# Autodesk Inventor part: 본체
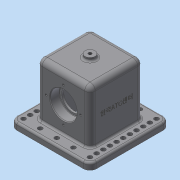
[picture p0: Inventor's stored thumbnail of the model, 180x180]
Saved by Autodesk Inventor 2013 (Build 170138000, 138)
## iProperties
Created: 2018-11
Part Number: 본체
Material: 일반
Document SubType Name: Modeling
Designer: dgall
Density: 1 g/cm^3
Author: dgall
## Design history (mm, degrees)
sketch "스케치1"
  geometry: L1 (-40, 40)-(40, 40); L2 (40, 40)-(40, -40); L3 (40, -40)-(-40, -40); L4 (-40, -40)-(-40, 40); L5 (-60, 60)-(60, 60); L6 (60, 60)-(60, -60); L7 (60, -60)-(-60, -60); L8 (-60, -60)-(-60, 60); L9 (-30, 23)-(30, 23); L10 (30, 23)-(30, -23); L11 (30, -23)-(-30, -23); L12 (-30, -23)-(-30, 23); 7 further points
  constraints: 24 end point, 6 midpoint, 6 parallel, 5 perpendicular, 3 horizontal, 3 horizontal alignment, 3 vertical alignment
  dimensions: "d0" = 80 distance of L1.start L1.end; "d2" = 120 distance of L5.start L5.end; "d14" = 60 distance of L9.start L9.end; "d15" = 46 distance of L11.end L9.start
extrude "돌출1" new body sketch "스케치1" distance "d3" = 90; taper "d4" = 0 deg
extrude "돌출2" join sketch "스케치1" distance "d5" = 10; taper "d6" = 0 deg
sketch "스케치2"
  geometry: L1 (60, 10)-(60, 0) reference; L2 (60, 0)-(-60, 0) reference; L3 (-60, 0)-(-60, 10) reference; L4 (-60, 10)-(-40, 10) reference; L5 (-40, 10)-(-40, 90) reference; L6 (-40, 90)-(40, 90) reference; L7 (40, 90)-(40, 10) reference; L8 (40, 10)-(60, 10) reference; L9 (-40, 48)-(40, 48); L10 (-40, 68)-(-26, 68); L11 (-26, 68)-(-26, 64.5); L12 (-26, 64.5)-(-23, 64.5); L13 (-23, 64.5)-(-23, 48); L14 (23, 64.5)-(26, 64.5); L15 (26, 64.5)-(26, 68); L16 (26, 68)-(40, 68); L17 (23, 64.5)-(23, 48); 1 further point
  constraints: 18 end point, 6 point on line, 5 parallel, 5 perpendicular, 3 equal length, 1 horizontal alignment
  dimensions: "d7" = 48 distance between parallel lines of L2 L9; "d8" = 14 distance of L10.start L10.end; "d9" = 3 distance of L11.end L12.end; "d11" = 40 diameter of L10 L9; "d12" = 33 diameter of L12 L9
revolve "회전1" sketch "스케치2" stored, may be unused: angle "d13" = 90 deg
extrude "돌출3" cut sketch "스케치1" distance "d16" = 80; taper "d17" = 0 deg
node "작업 평면1"
sketch "스케치5"
  geometry: C1 r 7.5 at (0, 0); 1 further point
  constraints: 1 centre point, 1 coincident
  dimensions: "d52" = 15 diameter of C1
extrude "돌출4" join sketch "스케치5" stored distance "d53" = 80; taper "d54" = 0 deg
hole "구멍3" diameter "d57" = 4.917; stored, may be unused: countersink angle "d61" = 90 deg, drill point angle "d63" = 0 deg; dims "d58" = 3, "d59" = 4, "d60" = 2, "d62" = 8, "d117" = 10, "d118" = 10
sketch "스케치6"
  geometry: C1 r 20 at (40, -42) reference; 2 further points
  constraints: 1 vertical alignment
  dimensions: "d64" = 26 distance of C1.centre point (40, -16)
hole "구멍4" sketch "스케치6" at (40, -16) diameter "d65" = 3.242; stored, may be unused: countersink angle "d69" = 90 deg, drill point angle "d71" = 118 deg; dims "d66" = 8, "d67" = 4, "d68" = 2, "d70" = 10
fillet "모깎기1" dims "d75" = 8
fillet "모깎기2" dims "d76" = 8
fillet "모깎기3" dims "d77" = 3
fillet "모깎기4" dims "d78" = 0.6
chamfer "모따기1" distance "d79" = 1; stored, may be unused: second distance "d80" = 2, angle "d81" = 45 deg
fillet "모깎기5" dims "d82" = 10
fillet "모깎기6" dims "d83" = 3
fillet "모깎기7" dims "d84" = 3
fillet "모깎기8" dims "d85" = 3
fillet "모깎기9" dims "d86" = 3
sketch "스케치7"
  geometry: A1 r 7 centre (-50, -50) between (-57, -50) and (-50, -57) reference; 4 further points
  constraints: 3 horizontal alignment
  dimensions: "d87" = 25 distance of A1.centre point (-25, -50); "d88" = 25 distance of point (-25, -50) point (0, -50); "d89" = 25 distance of point (25, -50) point (0, -50)
hole "구멍5" sketch "스케치7" at (-25, -50), (0, -50), (25, -50) diameter "d90" = 6.6; stored, may be unused: countersink angle "d94" = 90 deg, drill point angle "d96" = 0 deg; dims "d91" = 6.6, "d92" = 4, "d93" = 2, "d95" = 10
sketch "스케치8"
  geometry: A1 r 7 centre (-50, -50) between (-57, -50) and (-50, -57) reference; A2 r 7 centre (-50, 50) between (-50, 57) and (-57, 50) reference; 12 further points
  constraints: 10 vertical alignment, 2 coincident
  dimensions: "d97" = 10 distance of point (-50, -40) point (-50, -50); "d99" = 10 distance of point (-50, -30) point (-50, -40); "d100" = 10 distance of point (-50, -20) point (-50, -30); "d101" = 10 distance of point (-50, -10) point (-50, -20); "d102" = 10 distance of point (-50, 0) point (-50, -10); "d103" = 10 distance of point (-50, 10) point (-50, 0); "d104" = 10 distance of point (-50, 20) point (-50, 10); "d105" = 10 distance of point (-50, 30) point (-50, 20); "d106" = 10 distance of point (-50, 40) point (-50, 30)
hole "구멍6" sketch "스케치8" at (-50, 50), (-50, 40), (-50, 30), (-50, 20), (-50, 10), (-50, 0), (-50, -10), (-50, -20), (-50, -30), (-50, -40), (-50, -50) diameter "d107" = 6.6; stored, may be unused: countersink angle "d111" = 90 deg, drill point angle "d113" = 0 deg; dims "d108" = 6.6, "d109" = 4, "d110" = 2, "d112" = 10
sketch "스케치9"
  geometry: L1 (82, 82)-(82, -18) reference; 3 further points
  constraints: 1 horizontal alignment, 1 midpoint, 1 other
  dimensions: "d114" = 48 distance from line of L1 point (34, 32)
feature "엠보싱1" sketch "스케치9" dims "d0" = 80, "d2" = 120, "d7" = 48, "d8" = 14, "d9" = 3, "d11" = 40, "d12" = 33, "d115" = 0.5, "d116" = 0
node "솔리드1"
pattern_circular "원형 패턴1" dims angle "d73" = 360 deg
mirror "대칭3"
mirror "대칭4"
mirror "대칭5"
node "절단 모서리 투영1"
other parameters: "d51" = 5
